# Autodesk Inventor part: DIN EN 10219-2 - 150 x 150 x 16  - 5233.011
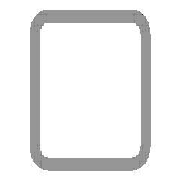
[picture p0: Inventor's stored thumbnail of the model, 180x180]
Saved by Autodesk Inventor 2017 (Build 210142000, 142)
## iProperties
Created: 2017-11
Part Number: DIN EN 10219-2 - 150 x 150 x 16  - 5233.011
Material: Steel, Mild
Description: Cold formed welded structural hollow sections of non-alloy and fine grain structural steel
Document SubType Name: Modeling
Standard: DIN
Designer: iusti
Standard Revision: 2006-07
Standards Organization: DIN
Language: en-US
Size Designation: 150 x 150 x 16
Categories: <MemberInstance><Categories><Category DisplayName="Structural Shapes" InternalName="089c4875-fa83-4c05-b084-43b9cc11f5ed" Mnemonic="GRDR"><CategoryParameter Dis
Stock Number: 150 x 150 x 16
Mass: 301820 g
Surface Area: 48238.1 cm^2
Volume: 38448.4 cm^3
Density: 7.85 g/cm^3
Appearance: Semi-Polished
IsCustomPart: 1
G_W: 150.000 mm
G_H: 150.000 mm
G_L: 5233.011 mm
+29768780-A419-4CF3-9340-1BC278E7B28F+CUTDETAIL2: Cut
+346FD258-9F9C-4BDE-884E-4FE9BE76FCEA+CUTDETAIL3: Miter 69.88 deg
_CCFamilyMember: 76
_CCFamilyDisplayName: DIN EN 10219-2 (Square Hollow Section - Cold Formed) - Cold formed welded structural hollow sections of non-alloy and fine grain structural steel
_FrameMemberDoc: Frame Member File
_Version: 15.0.0
_GetPNFromCC: 1
Author: iusti
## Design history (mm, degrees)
node "Start plane"
node "End plane"
sketch "Sketch"
  geometry: L1 (-75, -27)-(-75, 27); L2 (-27, 75)-(27, 75); L3 (75, 27)-(75, -27); L4 (27, -75)-(-27, -75); L5 (-27, 59)-(27, 59); L6 (59, 27)-(59, -27); L7 (27, -59)-(-27, -59); L8 (-59, -27)-(-59, 27); L9 (0, 118.918)-(0, -118.918) reference; L10 (-118.918, 0)-(118.918, 0) reference; A1 r 48 centre (-27, -27) between (-75, -27) and (-27, -75); A2 r 48 centre (-27, 27) between (-27, 75) and (-75, 27); A3 r 48 centre (27, 27) between (75, 27) and (27, 75); A4 r 48 centre (27, -27) between (27, -75) and (75, -27); A5 r 32 centre (-27, 27) between (-27, 59) and (-59, 27); A6 r 32 centre (27, 27) between (59, 27) and (27, 59); A7 r 32 centre (27, -27) between (27, -59) and (59, -27); A8 r 32 centre (-27, -27) between (-59, -27) and (-27, -59)
  constraints: 16 end point, 16 point on circle, 8 centre point, 8 tangent, 4 parallel, 3 equal radius, 2 perpendicular, 7 other
  dimensions: "d7" = 48 radius of A1 (= G_IR); "d10" = 150 distance between parallel lines of L2 L4 (= G_H); "d11" = 150 distance between parallel lines of L1 L3 (= G_W); "d12" = 16 distance between parallel lines of L3 L6 (= G_T); "d15" = 75 distance between parallel lines of L2 L10 (= 0.5 x d10); "d16" = 75 distance between parallel lines of L9 L3 (= 0.5 x d11)
extrude "Body" new body sketch "Sketch" stored distance "d3" = 5233.01077 (= G_L); taper "d4" = 0 deg
node "Driven Length"
  sketch "Sketch3"
    geometry: L1 (0, 0)-(10, 0) reference
    constraints: 2 end point, 1 horizontal
  workplane "Work Plane3"
  sketch "Sketch4"
    geometry: L1 (-2, 34.78)-(12, 34.78) reference; L2 (-2, 5267.791)-(12, 5267.791) reference
    dimensions: "d18" = 5233.01077 distance between parallel lines of L1 L2 (derived)
workplane "Work Plane5"
split "Split2"
workplane "Work Plane6"
split "Split3"
body "Solid1"
other parameters: "G_W" = 150 [user parameter; used in 1 equation term], "G_H" = 150 [user parameter; used in 1 equation term], "G_T" = 16 [user parameter; used in 1 equation term], "G_IR" = 48 [user parameter; used in 1 equation term], "G_L" = 5233.01077 (= d18) [user parameter; used in 1 equation term], "G_OFFSET_START" = -34.77977 [user parameter; used in 1 equation term], "G_OFFSET_END" = 27.4779 [user parameter; used in 1 equation term], "d13" = 34.77977 (= -G_OFFSET_START), "d14" = 5267.79054 (= G_OFFSET_END + B_L), "B_L" = 5240.31264 [user parameter; used in 1 equation term], "d17" = 90 deg
